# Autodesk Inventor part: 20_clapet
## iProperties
Created: 2002-11
Part Number: 20_clapet
Material: Par défaut
Document SubType Name: Modélisation
Designer: FIEVET
Control State: 0
Master: False
Checked Out: False
Shininess: 86.0
Length Units: 11269
Angle Units: 11279
Time Units: 11290
Mass Units: 11283
Length Display Precision: 3
Angle Display Precision: 2
Compacted: True
Density: 0.0
Volumn: 0.0
Area: 0.0
PropertySet Name: Model Information
Author: FIEVET
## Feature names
1. Extrusion1
